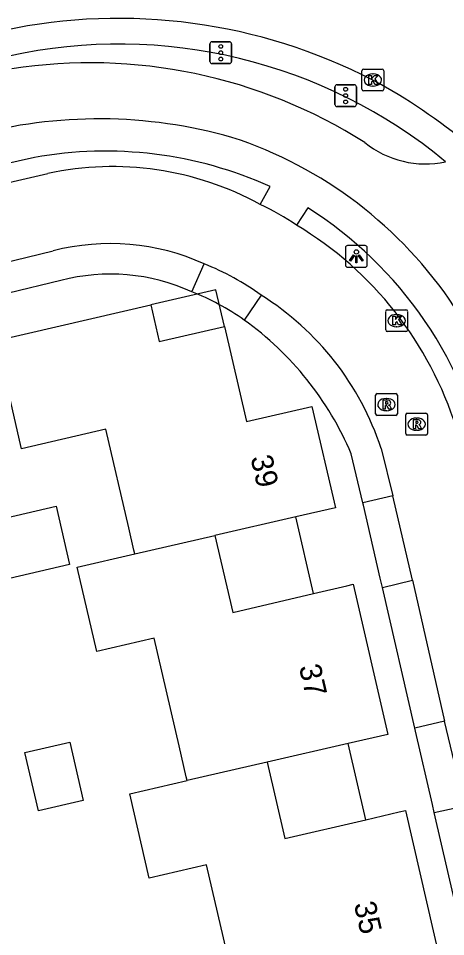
# Model space of a CAD drawing. Extents: x 156414 to 157775, y 382335 to 383765.
# Drawn here: x 156941.94 to 156961.53, y 382923.76 to 382965.87 of the extents above; entities that cross this region are included whole.
import ezdxf

# ---------------------------------------------------------------- set-up
doc = ezdxf.new("R2010")
doc.units = 0
for name, color, linetype in [('IMGEO_Berm_groen', 7, 'Continuous'), ('IMGEO_Fietspad_gesloten', 7, 'Continuous'), ('IMGEO_Kolk', 7, 'Continuous'), ('IMGEO_Lichtpunt', 7, 'Continuous'), ('IMGEO_Pand', 7, 'Continuous'), ('IMGEO_Pand_nummerreeks', 7, 'Continuous'), ('IMGEO_Pand_overbouw', 7, 'Continuous'), ('IMGEO_Rijbaan_lokaal_open', 7, 'Continuous'), ('IMGEO_Rijbaan_regionaal_gesloten', 7, 'Continuous'), ('IMGEO_Rioolput', 7, 'Continuous'), ('IMGEO_Verkeerseiland_open', 7, 'Continuous'), ('IMGEO_Verkeersregelinstallatiepaal', 7, 'Continuous'), ('IMGEO_Voetpad_open', 7, 'Continuous')]:
    doc.layers.add(name, color=color, linetype=linetype)

msp = doc.modelspace()

# ---------------------------------------------------------------- linework, layer by layer
at = {"layer": 'IMGEO_Berm_groen'}
for points in [[(156943.885, 382953.85), (156941.48, 382953.262)], [(156957.734, 382943.651), (156957.201, 382945.894)], [(156960.116, 382933.313), (156958.628, 382939.774)], [(156962.495, 382922.988), (156961.007, 382929.446)]]:
    msp.add_lwpolyline(points, dxfattribs=at)
for centre, radius, start, end in [((156946.148, 382945.089), 9.049, 65.6236, 104.4856), ((156943.77, 382940.19), 14.592, 23.0116, 54.2625)]:
    msp.add_arc(centre, radius, start, end, dxfattribs=at)
at = {"layer": 'IMGEO_Fietspad_gesloten'}
for centre, radius, start, end in [((156945.236, 382940.355), 23.474, 57.5864, 98.8301), ((156945.631, 382938.914), 22.343, 74.1693, 105.1195), ((156945.649, 382941.853), 19.526, 33.5501, 71.866), ((156960.594, 382963.613), 4.421, 231.1175, 282.1811)]:
    msp.add_arc(centre, radius, start, end, dxfattribs=at)
at = {"layer": 'IMGEO_Kolk'}
for p, q in [((156957.69, 382962.612), (156957.69, 382963.464)), ((156957.765, 382963.538), (156958.617, 382963.538)), ((156958.178, 382963.318), (156958.203, 382963.318)), ((156958.691, 382963.464), (156958.691, 382962.612)), ((156958.617, 382962.538), (156957.765, 382962.538)), ((156958.201, 382962.758), (156958.176, 382962.758)), ((156958.778, 382951.58), (156958.778, 382952.432)), ((156958.853, 382952.506), (156959.705, 382952.506)), ((156959.779, 382952.432), (156959.779, 382951.58)), ((156959.266, 382952.286), (156959.291, 382952.286)), ((156959.289, 382951.726), (156959.264, 382951.726)), ((156959.705, 382951.506), (156958.853, 382951.506))]:
    msp.add_line(p, q, dxfattribs=at)
for points in [[(156957.69, 382962.612), (156957.69, 382963.464)], [(156957.765, 382963.538), (156958.617, 382963.538)], [(156958.691, 382963.464), (156958.691, 382962.612)], [(156958.011, 382963.238), (156958.134, 382963.238), (156958.134, 382963.087), (156958.264, 382963.238), (156958.428, 382963.238), (156958.282, 382963.087), (156958.435, 382962.838), (156958.283, 382962.838), (156958.198, 382963.002), (156958.134, 382962.935), (156958.134, 382962.838), (156958.011, 382962.838), (156958.011, 382963.238)], [(156958.617, 382962.538), (156957.765, 382962.538)], [(156958.778, 382951.58), (156958.778, 382952.432)], [(156958.853, 382952.506), (156959.705, 382952.506)], [(156959.779, 382952.432), (156959.779, 382951.58)], [(156959.099, 382952.206), (156959.222, 382952.206), (156959.222, 382952.055), (156959.352, 382952.206), (156959.516, 382952.206), (156959.37, 382952.055), (156959.523, 382951.806), (156959.371, 382951.806), (156959.286, 382951.97), (156959.222, 382951.903), (156959.222, 382951.806), (156959.099, 382951.806), (156959.099, 382952.206)], [(156959.705, 382951.506), (156958.853, 382951.506)]]:
    msp.add_lwpolyline(points, dxfattribs=at)
for centre, start, end in [((156957.767, 382963.462), 91.552, 178.448), ((156957.767, 382963.462), 91.552, 178.448), ((156958.615, 382963.462), 1.552, 88.448), ((156958.615, 382963.462), 1.552, 88.448), ((156957.767, 382962.614), 181.552, 268.448), ((156957.767, 382962.614), 181.552, 268.448), ((156958.615, 382962.614), 271.552, 358.448), ((156958.615, 382962.614), 271.552, 358.448), ((156958.855, 382952.43), 91.552, 178.448), ((156958.855, 382952.43), 91.552, 178.448), ((156959.703, 382952.43), 1.552, 88.448), ((156959.703, 382952.43), 1.552, 88.448), ((156958.855, 382951.582), 181.552, 268.448), ((156958.855, 382951.582), 181.552, 268.448), ((156959.703, 382951.582), 271.552, 358.448), ((156959.703, 382951.582), 271.552, 358.448)]:
    msp.add_arc(centre, 0.0765, start, end, dxfattribs=at)
for centre, major_axis, ratio, start_param, end_param in [((156958.177, 382963.038), (-0.387, 0.002), 0.722429, 4.712389, 7.853982), ((156958.202, 382963.038), (-0.39, 0.002), 0.717154, 1.570796, 4.712389), ((156959.265, 382952.006), (-0.387, 0.002), 0.722429, 4.712389, 7.853982), ((156959.29, 382952.006), (-0.39, 0.002), 0.717154, 1.570796, 4.712389)]:
    msp.add_ellipse(centre, major_axis=major_axis, ratio=ratio, start_param=start_param, end_param=end_param, dxfattribs=at)
at = {"layer": 'IMGEO_Lichtpunt'}
for p, q in [((156956.936, 382955.355), (156956.936, 382954.548)), ((156956.936, 382955.355), (156956.936, 382954.548)), ((156957.838, 382955.45), (156957.03, 382955.45)), ((156957.838, 382955.45), (156957.03, 382955.45)), ((156957.932, 382954.548), (156957.932, 382955.355)), ((156957.932, 382954.548), (156957.932, 382955.355)), ((156957.03, 382954.454), (156957.838, 382954.454)), ((156957.03, 382954.454), (156957.838, 382954.454))]:
    msp.add_line(p, q, dxfattribs=at)
for points in [[(156957.31, 382955.019), (156957.349, 382954.991), (156957.161, 382954.729), (156957.123, 382954.756), (156957.31, 382955.019)], [(156957.412, 382954.971), (156957.459, 382954.971), (156957.459, 382954.649), (156957.412, 382954.649), (156957.412, 382954.971)], [(156957.522, 382954.991), (156957.56, 382955.018), (156957.747, 382954.756), (156957.708, 382954.728), (156957.522, 382954.991)]]:
    msp.add_lwpolyline(points, dxfattribs=at)
msp.add_circle((156957.435, 382955.153), 0.0994, dxfattribs=at)
for centre, start, end in [((156957.03, 382955.355), 90, 180), ((156957.03, 382955.355), 90, 180), ((156957.838, 382955.355), 0, 90), ((156957.838, 382955.355), 0, 90), ((156957.03, 382954.548), 180, 270), ((156957.03, 382954.548), 180, 270), ((156957.838, 382954.548), 270, 0), ((156957.838, 382954.548), 270, 360)]:
    msp.add_arc(centre, 0.0946, start, end, dxfattribs=at)
at = {"layer": 'IMGEO_Pand'}
for points in [[(156947.27, 382941.312), (156947.231, 382941.479), (156946.995, 382942.502), (156945.95, 382947.023), (156942.082, 382946.132), (156942.037, 382946.327), (156940.936, 382951.102), (156948.004, 382952.731), (156948.396, 382951.045), (156951.381, 382951.731), (156952.389, 382947.377), (156955.398, 382948.066), (156956.474, 382943.428), (156954.652, 382943.009), (156950.939, 382942.155)], [(156939.981, 382942.644), (156943.671, 382943.497), (156944.288, 382940.825), (156940.598, 382939.972), (156939.981, 382942.644)], [(156947.27, 382941.312), (156950.939, 382942.155)], [(156950.939, 382942.155), (156951.763, 382938.625), (156955.473, 382939.492), (156957.002, 382939.85), (156957.294, 382939.918), (156958.877, 382933.032), (156957.056, 382932.613), (156953.343, 382931.76)], [(156949.673, 382930.916), (156949.634, 382931.083), (156949.303, 382932.514), (156948.164, 382937.446), (156945.533, 382936.839), (156944.639, 382940.707), (156947.27, 382941.312)], [(156942.24, 382932.206), (156944.293, 382932.681), (156944.913, 382929.996), (156942.861, 382929.522), (156942.24, 382932.206)], [(156953.343, 382931.76), (156949.673, 382930.916)], [(156953.343, 382931.76), (156954.156, 382928.261), (156957.867, 382929.123), (156959.396, 382929.479), (156959.688, 382929.547), (156961.304, 382922.502), (156961.012, 382922.433), (156959.483, 382922.073), (156955.775, 382921.2)], [(156952.114, 382920.354), (156950.566, 382927.05), (156947.935, 382926.443), (156947.041, 382930.311), (156949.673, 382930.916)]]:
    msp.add_lwpolyline(points, dxfattribs=at)
at = {"layer": 'IMGEO_Pand_overbouw'}
for points in [[(156948.004, 382952.731), (156948.396, 382951.045), (156951.381, 382951.731), (156950.99, 382953.419)], [(156950.939, 382942.155), (156951.763, 382938.625), (156955.473, 382939.492), (156954.652, 382943.009)], [(156957.056, 382932.613), (156953.343, 382931.76), (156954.156, 382928.261), (156957.867, 382929.123)]]:
    msp.add_lwpolyline(points, close=True, dxfattribs=at)
at = {"layer": 'IMGEO_Rijbaan_lokaal_open'}
for points in [[(156922.072, 382953.868), (156943.287, 382958.756)], [(156941.148, 382954.622), (156943.531, 382955.205)], [(156958.566, 382946.144), (156959.106, 382943.965)], [(156959.106, 382943.965), (156957.734, 382943.651)], [(156960.013, 382940.109), (156959.106, 382943.965)], [(156958.628, 382939.774), (156958.531, 382940.198), (156957.757, 382943.551), (156957.734, 382943.651)], [(156958.628, 382939.774), (156960.013, 382940.109)], [(156960.013, 382940.109), (156961.48, 382933.643)], [(156961.48, 382933.643), (156960.116, 382933.313)], [(156962.404, 382929.759), (156961.48, 382933.643)], [(156961.007, 382929.446), (156960.923, 382929.812), (156960.147, 382933.18), (156960.116, 382933.313)], [(156961.007, 382929.446), (156962.404, 382929.759)]]:
    msp.add_lwpolyline(points, dxfattribs=at)
for centre, radius, start, end in [((156946.241, 382944.905), 14.162, 61.3539, 102.0386), ((156947.746, 382946.175), 12.347, 55.76, 64.6612), ((156946.165, 382942.136), 16.603, 17.3166, 59.0946), ((156946.147, 382945.087), 10.451, 65.6216, 104.4981), ((156946.338, 382944.041), 11.341, 53.6058, 68.6815), ((156946.185, 382942.119), 13.019, 18.0099, 58.0881)]:
    msp.add_arc(centre, radius, start, end, dxfattribs=at)
at = {"layer": 'IMGEO_Rijbaan_regionaal_gesloten'}
for centre, radius, start, end in [((156946.534, 382940.48), 25.385, 62.6759, 101.9417), ((156946.456, 382941.011), 24.951, 49.6908, 61.9574)]:
    msp.add_arc(centre, radius, start, end, dxfattribs=at)
at = {"layer": 'IMGEO_Rioolput'}
for p, q in [((156958.313, 382947.731), (156958.313, 382948.583)), ((156958.388, 382948.657), (156959.24, 382948.657)), ((156959.314, 382948.583), (156959.314, 382947.731)), ((156958.801, 382948.437), (156958.826, 382948.437)), ((156958.824, 382947.877), (156958.799, 382947.877)), ((156959.77, 382947.76), (156960.622, 382947.76)), ((156959.24, 382947.657), (156958.388, 382947.657)), ((156959.695, 382946.834), (156959.695, 382947.686)), ((156960.183, 382947.54), (156960.208, 382947.54)), ((156960.696, 382947.686), (156960.696, 382946.834)), ((156960.206, 382946.98), (156960.181, 382946.98)), ((156960.622, 382946.76), (156959.77, 382946.76))]:
    msp.add_line(p, q, dxfattribs=at)
for points in [[(156958.313, 382947.731), (156958.313, 382948.583)], [(156958.388, 382948.657), (156959.24, 382948.657)], [(156959.314, 382948.583), (156959.314, 382947.731)], [(156958.902, 382948.355), (156958.65, 382948.357), (156958.65, 382947.957)], [(156958.828, 382948.276), (156958.774, 382948.276), (156958.774, 382948.195)], [(156958.774, 382948.195), (156958.826, 382948.195)], [(156958.65, 382947.957), (156958.774, 382947.957), (156958.774, 382948.119), (156958.785, 382948.119)], [(156958.832, 382948.09), (156958.903, 382947.957), (156959.043, 382947.957), (156958.978, 382948.083)], [(156959.77, 382947.76), (156960.622, 382947.76)], [(156959.24, 382947.657), (156958.388, 382947.657)], [(156959.695, 382946.834), (156959.695, 382947.686)], [(156960.284, 382947.458), (156960.032, 382947.46), (156960.032, 382947.06)], [(156960.21, 382947.379), (156960.156, 382947.379), (156960.156, 382947.298)], [(156960.696, 382947.686), (156960.696, 382946.834)], [(156960.032, 382947.06), (156960.156, 382947.06), (156960.156, 382947.222), (156960.167, 382947.222)], [(156960.156, 382947.298), (156960.208, 382947.298)], [(156960.214, 382947.193), (156960.285, 382947.06), (156960.425, 382947.06), (156960.36, 382947.186)], [(156960.622, 382946.76), (156959.77, 382946.76)]]:
    msp.add_lwpolyline(points, dxfattribs=at)
for centre, radius, start, end in [((156958.39, 382948.581), 0.0765, 91.552, 178.448), ((156958.39, 382948.581), 0.0765, 91.552, 178.448), ((156959.238, 382948.581), 0.0765, 1.552, 88.448), ((156959.238, 382948.581), 0.0765, 1.552, 88.448), ((156958.81, 382948.384), 0.19, 274.7715, 282.9687), ((156958.834, 382948.18), 0.0964, 77.0061, 93.1865), ((156958.848, 382948.237), 0.0378, 276.6634, 79.6772), ((156958.901, 382948.245), 0.109, 350.3612, 89.416), ((156958.899, 382948.245), 0.112, 277.5842, 350.9817), ((156958.784, 382948.066), 0.0533, 26.0293, 88.6989), ((156958.883, 382948.03), 0.108, 29.5134, 73.7905), ((156959.772, 382947.684), 0.0765, 91.552, 178.448), ((156959.772, 382947.684), 0.0765, 91.552, 178.448), ((156960.62, 382947.684), 0.0765, 1.552, 88.448), ((156960.62, 382947.684), 0.0765, 1.552, 88.448), ((156958.39, 382947.733), 0.0765, 181.552, 268.448), ((156958.39, 382947.733), 0.0765, 181.552, 268.448), ((156959.238, 382947.733), 0.0765, 271.552, 358.448), ((156959.238, 382947.733), 0.0765, 271.552, 358.448), ((156960.216, 382947.283), 0.0964, 77.0061, 93.1865), ((156960.23, 382947.34), 0.0378, 276.6634, 79.6772), ((156960.283, 382947.348), 0.109, 350.3612, 89.416), ((156960.281, 382947.348), 0.112, 277.5842, 350.9817), ((156960.166, 382947.169), 0.0533, 26.0293, 88.6989), ((156960.192, 382947.487), 0.19, 274.7715, 282.9687), ((156960.265, 382947.133), 0.108, 29.5134, 73.7905), ((156959.772, 382946.836), 0.0765, 181.552, 268.448), ((156959.772, 382946.836), 0.0765, 181.552, 268.448), ((156960.62, 382946.836), 0.0765, 271.552, 358.448), ((156960.62, 382946.836), 0.0765, 271.552, 358.448)]:
    msp.add_arc(centre, radius, start, end, dxfattribs=at)
for centre, major_axis, ratio, start_param, end_param in [((156958.8, 382948.157), (-0.387, 0.002), 0.722429, 4.712389, 7.853982), ((156958.825, 382948.157), (-0.39, 0.002), 0.717154, 1.570796, 4.712389), ((156960.182, 382947.26), (-0.387, 0.002), 0.722429, 4.712389, 7.853982), ((156960.207, 382947.26), (-0.39, 0.002), 0.717154, 1.570796, 4.712389)]:
    msp.add_ellipse(centre, major_axis=major_axis, ratio=ratio, start_param=start_param, end_param=end_param, dxfattribs=at)
at = {"layer": 'IMGEO_Verkeerseiland_open'}
msp.add_arc((156946.547, 382941.181), 23.504, 50.4056, 102.3894, dxfattribs=at)
at = {"layer": 'IMGEO_Verkeersregelinstallatiepaal'}
for p, q in [((156950.721, 382963.891), (156950.721, 382964.691)), ((156950.721, 382964.691), (156950.721, 382963.891)), ((156950.821, 382964.791), (156951.611, 382964.791)), ((156951.611, 382964.791), (156950.821, 382964.791)), ((156951.711, 382964.691), (156951.711, 382963.891)), ((156951.711, 382963.891), (156951.711, 382964.691)), ((156951.611, 382963.791), (156950.821, 382963.791)), ((156950.821, 382963.791), (156951.611, 382963.791)), ((156956.447, 382961.923), (156956.447, 382962.723)), ((156956.447, 382962.723), (156956.447, 382961.923)), ((156956.547, 382962.823), (156957.337, 382962.823)), ((156957.337, 382962.823), (156956.547, 382962.823)), ((156957.437, 382962.723), (156957.437, 382961.923)), ((156957.437, 382961.923), (156957.437, 382962.723)), ((156957.337, 382961.823), (156956.547, 382961.823)), ((156956.547, 382961.823), (156957.337, 382961.823))]:
    msp.add_line(p, q, dxfattribs=at)
for centre in [(156951.216, 382964.581), (156951.216, 382964.291), (156951.216, 382964.001), (156956.942, 382962.613), (156956.942, 382962.323), (156956.942, 382962.033)]:
    msp.add_circle(centre, 0.085, dxfattribs=at)
for centre, start, end in [((156950.821, 382964.691), 90, 180), ((156950.821, 382964.691), 90, 180), ((156951.611, 382964.691), 0, 90), ((156951.611, 382964.691), 360, 90), ((156950.821, 382963.891), 180, 270), ((156950.821, 382963.891), 180, 270), ((156951.611, 382963.891), 270, 0), ((156951.611, 382963.891), 270, 0), ((156956.547, 382962.723), 90, 180), ((156956.547, 382962.723), 90, 180), ((156957.337, 382962.723), 0, 90), ((156957.337, 382962.723), 360, 90), ((156956.547, 382961.923), 180, 270), ((156956.547, 382961.923), 180, 270), ((156957.337, 382961.923), 270, 0), ((156957.337, 382961.923), 270, 0)]:
    msp.add_arc(centre, 0.1, start, end, dxfattribs=at)
at = {"layer": 'IMGEO_Voetpad_open'}
for points in [[(156942.674, 382959.488), (156921.828, 382954.805)], [(156953.03, 382957.334), (156953.481, 382958.155)], [(156955.209, 382957.18), (156954.693, 382956.382)], [(156949.883, 382953.331), (156950.461, 382954.606)], [(156953.067, 382953.17), (156952.293, 382952.034)]]:
    msp.add_lwpolyline(points, dxfattribs=at)
for centre, radius, start, end in [((156945.928, 382941.393), 18.385, 65.7426, 100.1941), ((156945.276, 382941.529), 18.537, 34.4495, 57.5985), ((156945.471, 382942.246), 11.931, 55.126, 68.298), ((156945.279, 382941.541), 18.527, 10.3497, 34.4235)]:
    msp.add_arc(centre, radius, start, end, dxfattribs=at)

# ---------------------------------------------------------------- texts
at = {"layer": 'IMGEO_Pand_nummerreeks'}
for s, rotation, p in [('39', 283.0632, (156952.574, 382945.728)), ('37', 283.0002, (156954.795, 382936.136)), ('35', 283.0002, (156957.313, 382925.256))]:
    msp.add_text(s, height=1, rotation=rotation, dxfattribs=at).set_placement(p)

doc.saveas('drawing.dxf')
